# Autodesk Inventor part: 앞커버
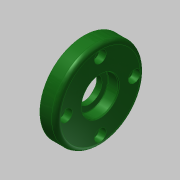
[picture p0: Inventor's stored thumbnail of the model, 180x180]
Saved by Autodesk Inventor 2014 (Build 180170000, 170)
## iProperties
Created: 2015-11
Part Number: 앞커버
Material: 알루미늄 6061
Document SubType Name: Modeling
Designer: mduedu
Density: 1 g/cm^3
Appearance: Smooth - Dark Forest Green
Author: mduedu
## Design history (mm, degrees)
sketch "스케치5"
  geometry: C1 r 30 at (0, 0); 2 further points
  constraints: 2 coincident, 1 centre point
  dimensions: "d66" = 60 diameter of C1
extrude "돌출2" new body sketch "스케치5" distance "d67" = 11; taper "d68" = 0 deg
sketch "스케치6"
  geometry: C1 r 16 at (0, 0); 1 further point
  constraints: 1 centre point, 1 coincident
  dimensions: "d69" = 32 diameter of C1
extrude "돌출3" join sketch "스케치6" distance "d70" = 3; taper "d71" = 0 deg
hole "구멍7" diameter "d98" = 25; stored, may be unused: countersink angle "d102" = 90 deg, drill point angle "d104" = 0 deg; dims "d96" = 10, "d97" = 10, "d99" = 6, "d100" = 4, "d101" = 2, "d103" = 3
hole "구멍8" diameter "d107" = 25; stored, may be unused: countersink angle "d111" = 90 deg, drill point angle "d113" = 0 deg; dims "d108" = 6, "d109" = 4, "d110" = 2, "d112" = 7.3, "d143" = 10, "d144" = 10
hole "구멍9" diameter "d116" = 17; stored, may be unused: countersink angle "d120" = 90 deg, drill point angle "d122" = 0 deg; dims "d114" = 10, "d115" = 10, "d117" = 6, "d118" = 4, "d119" = 2, "d121" = 7.7
chamfer "모따기2" distance "d123" = 0.7; stored, may be unused: second distance "d124" = 2, angle "d125" = 30 deg
fillet "모깎기11" dims "d126" = 0.3
fillet "모깎기13" dims "d128" = 3
fillet "모깎기14" dims "d129" = 3
fillet "모깎기15" dims "d130" = 0.3
sketch "스케치8" dims "d131" = 46
  geometry: 3 further points
  constraints: 2 vertical alignment, 1 coincident, 2 other
hole "구멍10" sketch "스케치8" at (0, 23) diameter "d132" = 4.5; stored, may be unused: countersink angle "d136" = 90 deg, drill point angle "d138" = 0 deg; dims "d133" = 6, "d134" = 8, "d135" = 4.6, "d137" = 7.7
node "솔리드2"
pattern_circular "원형 패턴4" dims angle "d140" = 360 deg
